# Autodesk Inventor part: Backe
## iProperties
Created: 2005-05
Part Number: Backe
Document SubType Name: Modeling
Designer: rsc
Manufacturer: Standard
Standards Organization: Custom
Description: Stellklotz
Vendor: Ettinger
Material: Al 99 F8
Category: Katalogteil
__ICENTER__: VpEWjrdpDpK1mcsYxBHpAaD70C0vtZVHcHAUWBXeUb5jjJpTdefGeyHiSKQ9/ugfLbAFafpfj5Xai+zAhL3iTy3oVkni1mMNNiN9tePP/U8yEHV4zf0Z0UgFhsTzU3Uv9jmNidwGjHW3DWAsQhkBd8/UDBzpa8Jv
__ICENTER_VERSION__: 2.0.8
Bestellbenennung: Gewinde-Nietelement
Bestellnummer: 5.60.842
b: 4,000 mm
Author: rsc
Comments: genietet 2mm
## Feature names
1. Extrusion4
